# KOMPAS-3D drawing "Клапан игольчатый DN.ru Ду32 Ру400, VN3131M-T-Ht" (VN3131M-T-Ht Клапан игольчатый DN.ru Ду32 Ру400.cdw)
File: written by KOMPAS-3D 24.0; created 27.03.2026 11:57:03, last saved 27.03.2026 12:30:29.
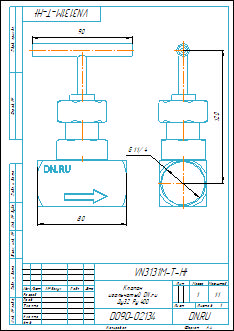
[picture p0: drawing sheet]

Document properties: Автор: Илья; Форматы листов документа: A4; Полное имя файла: VN3131M-T-Ht Клапан игольчатый DN.ru Ду32 Ру400.m3d; Масса: 1; Наименование: Клапан игольчатый DN.ru Ду32 Ру400; Количество листов документа: 1; Примечание: D090-02134

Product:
- Body: Body10  | qty 1
    Масса: 1.287778
- Part/product: Клапан игольчатый DN.ru Ду32 Ру400  | designation VN3131M-T-Ht
    Масса: 1
    Раздел спецификации: Прочие изделия
    Примечание: D090-02134

Views: Вид 1, Слева
Referenced files in D:\Обмен\Заказы с фриланса\DN.ru\VNxxM-T-Ht Клапан игольчатый DN.ru Ду8-50 Ру400\VN3232M-T-Ht Клапан игольчатый DN.ru Ду8-50 Ру400\DN8\: VN3232M-T-Ht Клапан игольчатый DN.ru Ду8 Ру400.m3d, VN3232M-T-Ht Клапан игольчатый DN.ru Ду8 Ру400.cdw
Referenced files in D:\Обмен\Заказы с фриланса\DN.ru\VNxxM-T-Ht Клапан игольчатый DN.ru Ду8-50 Ру400\VN3131M-T-Ht Клапан игольчатый DN.ru Ду8-50 Ру400\DN32\: VN3131M-T-Ht Клапан игольчатый DN.ru Ду32 Ру400.m3d
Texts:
  VN3131M-T-Ht
  Клапан
  игольчатый DN.ru
  Ду32 Ру400
  Body10
  Клапан игольчатый DN.ru Ду32 Ру400
  VN3131M-T-Ht Клапан игольчатый DN.ru Ду32 Ру400
Dimensions and other numbers on the sheet: 0; 3; 2; 4; 80; 90; 1:1; 1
